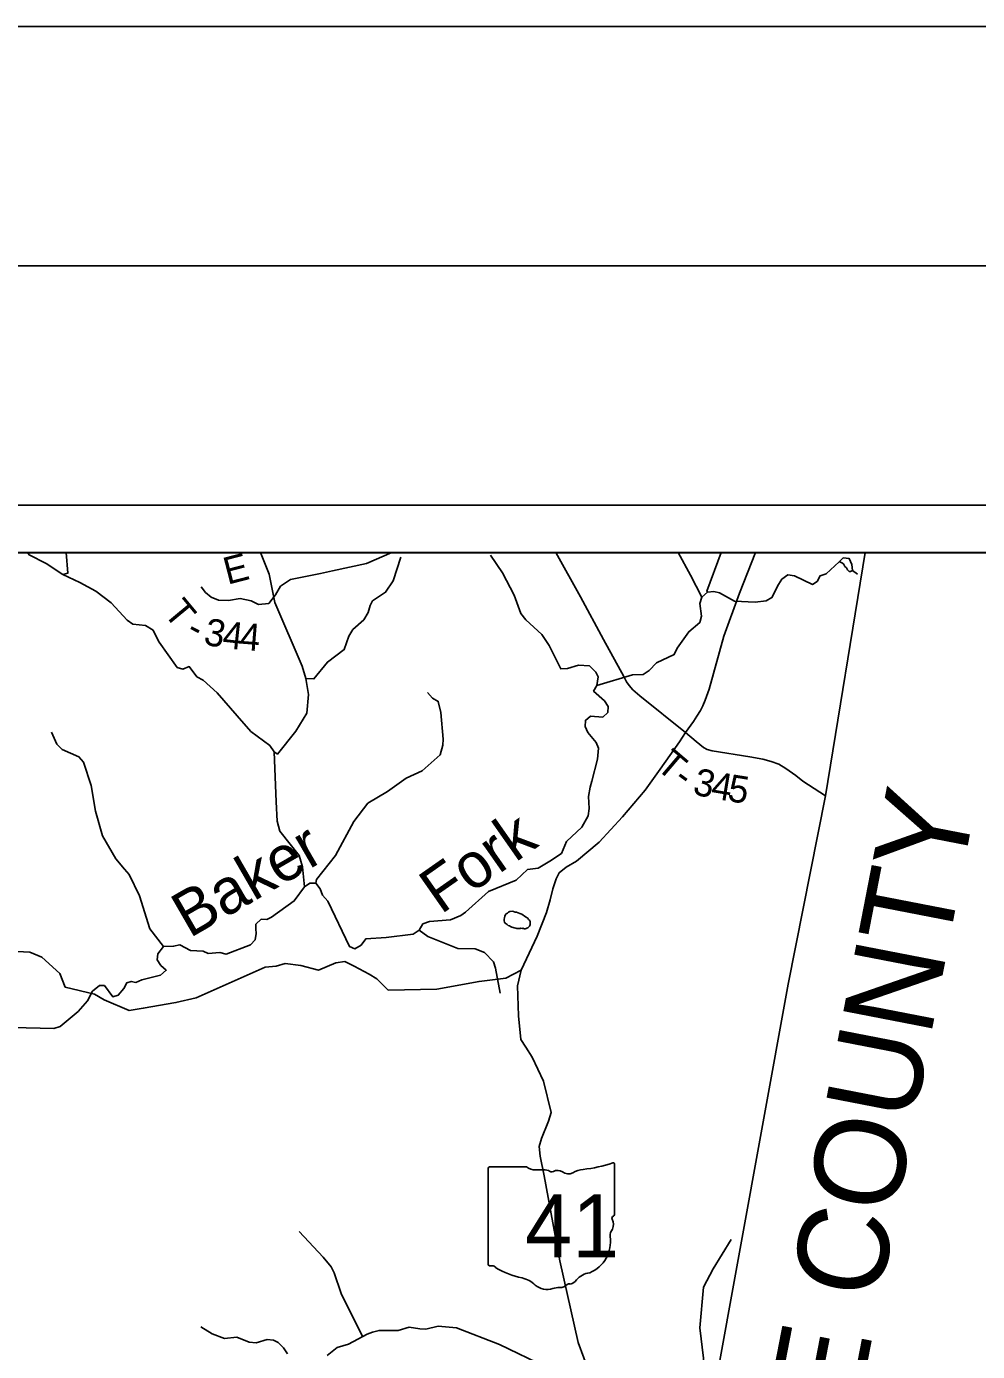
# Model space of a CAD drawing. Extents: x 0 to 34, y 0 to 22.
# Drawn here: x 5.858 to 7.846, y 19.231 to 22 of the extents above; entities that cross this region are included whole.
import ezdxf

# ---------------------------------------------------------------- set-up
doc = ezdxf.new("R2010")
doc.units = 0
for name, color, linetype in [('GM_X_Adjacent_County', 7, 'Continuous'), ('GM_X_Adjacent_County_Text', 7, 'Continuous'), ('GM_X_County', 7, 'Continuous'), ('GM_X_Major_River', 7, 'Continuous'), ('GM_X_Major_River_Text', 7, 'Continuous'), ('GM_X_Minor_Lake', 7, 'Continuous'), ('GM_X_Minor_River', 7, 'Continuous'), ('GM_X_State_Route', 7, 'Continuous'), ('GM_X_State_Shield', 7, 'Continuous'), ('GM_X_Township_Road', 7, 'Continuous'), ('GM_X_Township_Road_Text', 7, 'Continuous'), ('SH_Border', 7, 'Continuous'), ('SH_Cut_Line', 7, 'Continuous'), ('SH_Data', 7, 'Continuous')]:
    doc.layers.add(name, color=color, linetype=linetype)

msp = doc.modelspace()

# ---------------------------------------------------------------- linework, layer by layer
at = {"layer": 'GM_X_Adjacent_County'}
for points in [[(7.6111, 20.9006), (7.6101, 20.8946)], [(9.4, 14.9965), (9.4, 20.9006), (7.6111, 20.9006)]]:
    msp.add_lwpolyline(points, dxfattribs=at)
at = {"layer": 'GM_X_County'}
for points in [[(7.6111, 20.9006), (2.6, 20.9006), (2.6, 14.46)], [(6.5214, 15.204), (6.5756, 15.5109), (6.5797, 15.5314), (6.7601, 16.3985), (6.794, 16.5922), (6.9912, 17.4939), (7.1423, 18.303), (7.4503, 19.9984), (7.5281, 20.392), (7.6111, 20.9006)]]:
    msp.add_lwpolyline(points, dxfattribs=at)
at = {"layer": 'GM_X_Major_River'}
for points in [[(7.1594, 20.6542), (7.1471, 20.6461), (7.1247, 20.6454), (7.0502, 20.6228), (7.0436, 20.6111), (7.066, 20.5906), (7.0737, 20.579), (7.0735, 20.5665), (7.0627, 20.5568), (7.0373, 20.5588), (7.0265, 20.5499), (7.0262, 20.5373), (7.0313, 20.5247), (7.0488, 20.5035), (7.0535, 20.4916), (7.0515, 20.4689), (7.0396, 20.4227), (7.036, 20.4106), (7.033, 20.3909), (7.0344, 20.3658), (7.0322, 20.3503), (7.0189, 20.3266), (6.9872, 20.2971), (6.9764, 20.2715), (6.9518, 20.2556), (6.9276, 20.2412), (6.9056, 20.2382), (6.8816, 20.2162), (6.8238, 20.1922), (6.7759, 20.149), (6.7659, 20.1423), (6.7441, 20.1332), (6.7004, 20.1294), (6.6866, 20.1244), (6.6791, 20.1116), (6.6661, 20.1031), (6.6101, 20.0965), (6.5672, 20.0931), (6.5574, 20.0803), (6.5447, 20.0722), (6.5331, 20.0777), (6.4882, 20.172), (6.477, 20.1844), (6.4723, 20.1978), (6.463, 20.2097), (6.4505, 20.2095), (6.439, 20.2018), (6.4179, 20.1725), (6.3706, 20.1384), (6.3606, 20.134), (6.3485, 20.1343), (6.3376, 20.1238), (6.3378, 20.1143), (6.338, 20.1048), (6.3363, 20.0915), (6.3266, 20.0807), (6.2753, 20.0611), (6.2625, 20.0651), (6.2381, 20.0625), (6.2276, 20.0673), (6.2011, 20.0693), (6.1785, 20.0807), (6.1655, 20.0779), (6.1446, 20.0775), (6.133, 20.0622), (6.1316, 20.0496), (6.1393, 20.0377), (6.1505, 20.0276), (6.1386, 20.0176), (6.0996, 20.0079)], [(5.8289, 19.9079), (5.9151, 19.9059), (5.9284, 19.9099), (5.9662, 19.9414), (5.9861, 19.9636), (5.9961, 19.9839), (6.011, 19.9959), (6.0212, 19.9958), (6.0384, 19.9725), (6.0501, 19.9758), (6.062, 19.9893), (6.0678, 20.0014), (6.0773, 20.0043), (6.0871, 20.0024), (6.0996, 20.0079)]]:
    msp.add_lwpolyline(points, dxfattribs=at)
at = {"layer": 'GM_X_Minor_Lake'}
for points in [[(6.8683, 20.1507), (6.8656, 20.1488), (6.8633, 20.1473), (6.8611, 20.1454), (6.8588, 20.1431), (6.858, 20.1408), (6.8573, 20.137), (6.8565, 20.1347), (6.8569, 20.1329), (6.8569, 20.131), (6.8573, 20.1279), (6.8588, 20.126), (6.8611, 20.1245), (6.8629, 20.1234), (6.8648, 20.1215), (6.8675, 20.1207), (6.8698, 20.1192), (6.8724, 20.1177), (6.8751, 20.1169), (6.8773, 20.1162), (6.8811, 20.1154), (6.8834, 20.115), (6.8898, 20.115), (6.8917, 20.1154), (6.894, 20.115), (6.8963, 20.1154), (6.8986, 20.1146), (6.9008, 20.1146), (6.9058, 20.1162), (6.9077, 20.1177), (6.9092, 20.1196), (6.9103, 20.1215), (6.9107, 20.1234), (6.9111, 20.1264), (6.9111, 20.1298), (6.9096, 20.1321), (6.9077, 20.134), (6.9058, 20.1366), (6.9012, 20.1397), (6.8986, 20.1412), (6.8963, 20.1431), (6.8933, 20.1446), (6.8914, 20.1454), (6.8891, 20.1465), (6.8823, 20.1488), (6.8796, 20.1492), (6.8758, 20.1503), (6.8736, 20.1511), (6.8683, 20.1507)], [(6.8683, 20.1507), (6.8656, 20.1488), (6.8633, 20.1473), (6.8611, 20.1454), (6.8588, 20.1431), (6.858, 20.1408), (6.8573, 20.137), (6.8565, 20.1347), (6.8569, 20.1329), (6.8569, 20.131), (6.8573, 20.1279), (6.8588, 20.126), (6.8611, 20.1245), (6.8629, 20.1234), (6.8648, 20.1215), (6.8675, 20.1207), (6.8698, 20.1192), (6.8724, 20.1177), (6.8751, 20.1169), (6.8773, 20.1162), (6.8811, 20.1154), (6.8834, 20.115), (6.8898, 20.115), (6.8917, 20.1154), (6.894, 20.115)], [(6.894, 20.115), (6.8963, 20.1154), (6.8986, 20.1146), (6.9008, 20.1146), (6.9058, 20.1162), (6.9077, 20.1177), (6.9092, 20.1196), (6.9103, 20.1215), (6.9107, 20.1234), (6.9111, 20.1264), (6.9111, 20.1298), (6.9096, 20.1321), (6.9077, 20.134), (6.9058, 20.1366), (6.9012, 20.1397), (6.8986, 20.1412), (6.8963, 20.1431), (6.8933, 20.1446), (6.8914, 20.1454), (6.8891, 20.1465), (6.8823, 20.1488), (6.8796, 20.1492), (6.8758, 20.1503), (6.8736, 20.1511), (6.8683, 20.1507)]]:
    msp.add_lwpolyline(points, dxfattribs=at)
at = {"layer": 'GM_X_Minor_River'}
for points in [[(6.439, 20.2018), (6.4348, 20.244), (6.4284, 20.2673), (6.3876, 20.3182), (6.3823, 20.3396), (6.3804, 20.3795), (6.3756, 20.4845), (6.3671, 20.4971), (6.3274, 20.5267), (6.2988, 20.5595), (6.2568, 20.6078), (6.2276, 20.6338), (6.2145, 20.6409), (6.1985, 20.6624), (6.1852, 20.657), (6.1734, 20.6602), (6.1353, 20.7137), (6.1298, 20.7241), (6.1229, 20.7382), (6.1071, 20.748), (6.0806, 20.7508), (6.069, 20.7594), (6.0355, 20.7957), (6.0033, 20.8202), (5.9699, 20.8383), (5.9345, 20.8549), (5.8992, 20.8775), (5.8635, 20.8957), (5.8602, 20.9006)], [(5.9345, 20.8549), (5.9444, 20.8573), (5.9409, 20.9006)], [(6.3756, 20.4845), (6.3827, 20.4794), (6.4212, 20.5277), (6.4443, 20.5653), (6.4477, 20.604), (6.4418, 20.6371), (6.4344, 20.6631), (6.3773, 20.7964), (6.3752, 20.8066), (6.3655, 20.8555), (6.3475, 20.9006)], [(6.4418, 20.6371), (6.4589, 20.6364), (6.4873, 20.6717), (6.5223, 20.698), (6.5316, 20.7259), (6.5402, 20.7395), (6.563, 20.7603), (6.5724, 20.7754), (6.5765, 20.7897), (6.5816, 20.7995), (6.6089, 20.8176), (6.6249, 20.8417), (6.6406, 20.8908)], [(7.0502, 20.6228), (7.0529, 20.6409), (7.0481, 20.6509), (7.0347, 20.6641), (7.0119, 20.6656), (6.9886, 20.6581), (6.975, 20.6579), (6.9508, 20.7066), (6.9353, 20.7297), (6.9021, 20.7599), (6.8913, 20.7734), (6.8772, 20.8113), (6.8534, 20.8581), (6.8279, 20.8954)], [(7.1594, 20.6542), (7.1748, 20.6702), (7.2119, 20.6875), (7.2181, 20.7011), (7.2425, 20.735), (7.2656, 20.7545), (7.2692, 20.7677), (7.2654, 20.794), (7.2697, 20.8072), (7.2816, 20.8177), (7.2946, 20.8195), (7.3063, 20.8167), (7.3383, 20.7988), (7.3815, 20.7971), (7.404, 20.7999), (7.4162, 20.8065), (7.4299, 20.8337), (7.4369, 20.845), (7.4491, 20.8544), (7.4632, 20.8519), (7.5009, 20.834), (7.5108, 20.8403), (7.517, 20.852), (7.5296, 20.8564), (7.5569, 20.8816)], [(7.2199, 20.9006), (7.2461, 20.8535), (7.2697, 20.8072)], [(7.2816, 20.8177), (7.2798, 20.8199), (7.31, 20.9006)], [(7.5569, 20.8816), (7.5654, 20.8894), (7.5779, 20.8881), (7.5834, 20.8758), (7.5848, 20.8633), (7.5947, 20.8553)], [(7.5569, 20.8816), (7.5592, 20.8803), (7.5626, 20.8791), (7.566, 20.8768), (7.5689, 20.8718), (7.5719, 20.8684), (7.5742, 20.8642), (7.5775, 20.8611), (7.5802, 20.8611), (7.5848, 20.8633)], [(6.463, 20.2097), (6.4647, 20.2176), (6.5044, 20.2678), (6.5425, 20.3386), (6.5717, 20.3768), (6.6128, 20.4012), (6.6517, 20.4289), (6.6854, 20.4447), (6.7225, 20.4782), (6.7286, 20.4982), (6.7288, 20.5104), (6.7245, 20.5667), (6.7189, 20.5896), (6.7069, 20.5966), (6.6961, 20.6082)], [(6.1446, 20.0775), (6.1161, 20.1141), (6.0946, 20.1833), (6.0727, 20.2281), (6.063, 20.2389), (6.0448, 20.2609), (6.0172, 20.3085), (6.0026, 20.3605), (5.9934, 20.4138), (5.9776, 20.4624), (5.9679, 20.4739), (5.9325, 20.489), (5.9217, 20.5002), (5.9104, 20.5251)], [(6.6791, 20.1116), (6.6967, 20.098), (6.7597, 20.0733), (6.7957, 20.0722), (6.8157, 20.065), (6.8343, 20.045), (6.8386, 20.032), (6.8485, 19.9796)], [(6.5607, 19.2624), (6.5157, 19.3525), (6.5014, 19.3955), (6.4951, 19.4081), (6.4786, 19.428), (6.4281, 19.4815)], [(7.2301, 18.867), (7.2266, 18.8843), (7.2308, 18.9082), (7.248, 18.9409), (7.2583, 18.9689), (7.2651, 19.0158), (7.2647, 19.0409), (7.2561, 19.1226), (7.2591, 19.1446), (7.2707, 19.1846), (7.2731, 19.2172), (7.2654, 19.2807), (7.2735, 19.3656), (7.2935, 19.4041), (7.3308, 19.4654)], [(6.2229, 19.2823), (6.2466, 19.2676), (6.2723, 19.2583), (6.298, 19.2611), (6.3233, 19.2506), (6.338, 19.2493), (6.3615, 19.2559), (6.3744, 19.2546), (6.3842, 19.25), (6.3954, 19.2385), (6.4036, 19.2259)], [(6.4868, 19.2224), (6.5074, 19.2393), (6.5309, 19.2466), (6.5701, 19.2675), (6.5811, 19.2711), (6.5952, 19.2752), (6.6349, 19.2752), (6.658, 19.2818), (6.6803, 19.2781), (6.6928, 19.278), (6.7186, 19.2838), (6.7568, 19.2808), (6.8465, 19.2454), (6.9451, 19.1985)]]:
    msp.add_lwpolyline(points, dxfattribs=at)
at = {"layer": 'GM_X_State_Route'}
for points in [[(7.1063, 18.9936), (7.0115, 19.2499), (6.9726, 19.4202), (6.9402, 19.5983), (6.9316, 19.6394), (6.9295, 19.6592), (6.9347, 19.6762), (6.9495, 19.7121), (6.9546, 19.7307), (6.9391, 19.7962), (6.9154, 19.8458), (6.902, 19.8669), (6.8916, 19.8829), (6.8865, 19.9324), (6.8842, 19.9951), (6.8922, 20.028), (6.9253, 20.099), (6.9453, 20.1484), (6.9527, 20.1752), (6.9582, 20.198), (6.9651, 20.2191), (6.9714, 20.2315), (6.9865, 20.243), (7.008, 20.2559), (7.0548, 20.2952), (7.1038, 20.3486), (7.151, 20.4042), (7.1825, 20.448), (7.2231, 20.5048), (7.2357, 20.5243), (7.252, 20.5474), (7.2589, 20.5588), (7.267, 20.5706), (7.2719, 20.5803), (7.2767, 20.5921), (7.2853, 20.6149), (7.3158, 20.7256), (7.3485, 20.8158), (7.382, 20.9006)], [(7.2357, 20.5243), (7.1403, 20.6015), (7.1257, 20.614), (7.118, 20.6226), (7.1125, 20.6305), (7.1064, 20.6413), (7.0642, 20.7192), (7.0158, 20.8078), (6.9648, 20.9006)]]:
    msp.add_lwpolyline(points, dxfattribs=at)
at = {"layer": 'GM_X_State_Shield'}
for p, q in [((6.8234, 19.6135), (6.8234, 19.4134)), ((6.9032, 19.6169), (6.826, 19.6169)), ((7.087, 19.5172), (7.087, 19.6219)), ((7.087, 19.5172), (7.087, 19.5172))]:
    msp.add_line(p, q, dxfattribs=at)
for centre, radius, start, end in [((6.8264, 19.6139), 0.00305, 98.1301, 188.1301), ((6.9216, 19.6402), 0.0296, 231.6195, 271.1119), ((6.9314, 19.5046), 0.1064, 80.4867, 94.9883), ((6.9555, 19.615), 0.00855, 219.7921, 297.1024), ((6.9681, 19.5918), 0.0178, 54.4667, 119.1411), ((6.991, 19.6236), 0.0214, 233.8562, 294.8282), ((7.0288, 19.5558), 0.0563, 97.3462, 120.7689), ((6.9931, 19.8898), 0.2796, 275.8445, 288.9065), ((7.0841, 19.6223), 0.00294, 351.8621, 97.738), ((7.0864, 19.5095), 0.00454, 107.944, 210.337), ((7.0575, 19.4963), 0.0273, 340.033, 23.6496), ((7.0839, 19.5168), 0.00314, 289.6038, 7.7341), ((7.0088, 19.4601), 0.0699, 292.3089, 8.9858), ((7.0976, 19.4734), 0.0198, 136.8065, 186.9296), ((6.8264, 19.4129), 0.00308, 171.9584, 258.3066), ((6.8269, 19.4334), 0.0235, 267.339, 280.6039), ((6.8317, 19.4018), 0.00848, 29.7484, 93.2717), ((6.9388, 19.5816), 0.2019, 240.4129, 257.1985), ((6.8786, 19.3235), 0.0632, 47.1842, 75.836), ((7.0383, 19.3572), 0.0383, 94.4031, 142.5768), ((6.9469, 19.4008), 0.0401, 230.7004, 286.2918), ((6.9701, 19.3317), 0.0329, 85.6951, 111.2099), ((6.973, 19.3859), 0.0214, 268.777, 315.5493), ((6.9923, 19.3665), 0.00601, 65.7517, 132.6484), ((6.9897, 19.394), 0.0226, 282.8732, 323.2771)]:
    msp.add_arc(centre, radius, start, end, dxfattribs=at)
at = {"layer": 'GM_X_Township_Road'}
for points in [[(6.2232, 20.829), (6.2323, 20.8174), (6.2442, 20.8073), (6.2596, 20.8012), (6.2804, 20.8007), (6.3048, 20.8047), (6.3275, 20.7996), (6.3428, 20.7924), (6.3645, 20.7945), (6.379, 20.812), (6.3889, 20.8304), (6.4097, 20.844), (6.473, 20.8569), (6.4977, 20.8622), (6.5687, 20.8775), (6.6217, 20.9006)], [(7.2357, 20.5243), (7.2581, 20.5056), (7.2735, 20.493), (7.2808, 20.489), (7.2914, 20.4865), (7.3697, 20.4735), (7.3969, 20.4687), (7.4148, 20.4642), (7.4306, 20.4581), (7.4453, 20.4492), (7.466, 20.4346), (7.4805, 20.4232), (7.5281, 20.392)], [(5.8251, 20.0674), (5.8649, 20.0653), (5.8901, 20.0548), (5.928, 20.0208), (5.9391, 19.9921), (6.0003, 19.9779), (6.0208, 19.9658), (6.0727, 19.9439), (6.0852, 19.9458)], [(6.0852, 19.9458), (6.0982, 19.9477), (6.1023, 19.9483), (6.1705, 19.96), (6.2127, 19.9704), (6.3574, 20.0339), (6.3804, 20.0366), (6.3989, 20.0419), (6.4318, 20.0374), (6.4684, 20.0278), (6.5048, 20.0432), (6.5239, 20.0462), (6.5433, 20.0362), (6.5744, 20.0195), (6.5905, 20.01), (6.6144, 19.9858), (6.7159, 19.9885), (6.8042, 20.0044), (6.8599, 20.0109), (6.8922, 20.028)]]:
    msp.add_lwpolyline(points, dxfattribs=at)
at = {"layer": 'SH_Border'}
msp.add_lwpolyline([(2, 21.5), (33.5, 21.5), (33.5, 0.5), (2, 0.5)], close=True, dxfattribs=at)
at = {"layer": 'SH_Cut_Line'}
msp.add_lwpolyline([(0, 0), (34, 0), (34, 22), (0, 22)], close=True, dxfattribs=at)
at = {"layer": 'SH_Data'}
for p, q in [((2.5, 21), (9.5, 21)), ((2.6, 20.9), (9.4, 20.9))]:
    msp.add_line(p, q, dxfattribs=at)

# ---------------------------------------------------------------- texts
at = {"layer": 'GM_X_Adjacent_County_Text'}
msp.add_text('PIKE COUNTY', height=0.189394, rotation=79.0186, dxfattribs=at).set_placement((7.5169, 18.6977))
at = {"layer": 'GM_X_Major_River_Text'}
for s, rotation, p in [('Fork', 35.0018, (6.7241, 20.1432)), ('Baker', 30.0015, (6.1988, 20.0938))]:
    msp.add_text(s, height=0.0947, rotation=rotation, dxfattribs=at).set_placement(p)
at = {"layer": 'GM_X_State_Shield'}
msp.add_text('41', height=0.13184, dxfattribs=at).set_placement((6.9005, 19.4275))
at = {"layer": 'GM_X_Township_Road_Text'}
for s, rotation, p in [('E', 14.4853, (6.2784, 20.8332)), ('T', 309.6497, (6.1429, 20.774)), ('-', 332.5137, (6.1891, 20.7258)), ('3', 348.7973, (6.2263, 20.7092)), ('4', 353.8387, (6.2661, 20.7016)), ('4', 355.471, (6.3026, 20.6977)), ('T', 319.5716, (7.1714, 20.4509)), ('-', 323.905, (7.2074, 20.4204)), ('3', 346.667, (7.2484, 20.3964)), ('4', 350.7022, (7.2868, 20.3875)), ('5', 350.7328, (7.3214, 20.3818))]:
    msp.add_text(s, height=0.0568, rotation=rotation, dxfattribs=at).set_placement(p)

doc.saveas('drawing.dxf')
